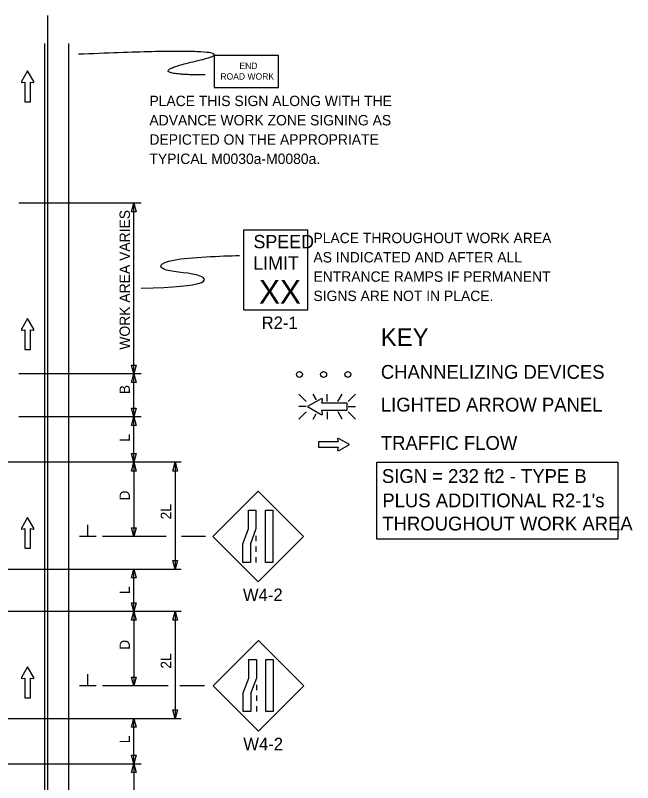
# Model space of a CAD drawing. Extents: x 16473 to 18475, y 7005 to 8296.
# Drawn here: x 17006 to 17422, y 7718 to 8234 of the extents above; entities that cross this region are included whole.
import ezdxf

# ---------------------------------------------------------------- set-up
doc = ezdxf.new("R2010")
doc.units = 0
for name, color, linetype in [('ALI_LEGAL_EX', 7, 'Continuous'), ('MT_SCRATCH_LEVEL_E', 7, 'Continuous'), ('PAVT_EDGE_EX', 7, 'Continuous'), ('TRAFFIC_SIGNS_PR', 7, 'Continuous'), ('TYPICAL_TEXT_DIMEN_EX', 7, 'Continuous'), ('TYPICAL_TEXT_DIMEN_PR', 7, 'Continuous')]:
    doc.layers.add(name, color=color, linetype=linetype)

msp = doc.modelspace()

# ---------------------------------------------------------------- linework, layer by layer
at = {"layer": 'ALI_LEGAL_EX'}
msp.add_line((17028.11, 8234.45), (17028.11, 7405.27), dxfattribs=at)
msp.add_line((17028.11, 8234.45), (17028.11, 7405.27), dxfattribs=at)
at = {"layer": 'MT_SCRATCH_LEVEL_E'}
for p, q in [((17014.65, 8197.08), (17010.54, 8189.84)), ((17018.8, 8189.84), (17014.65, 8197.08)), ((17011.03, 8189.16), (17012.8, 8189.47)), ((17012.8, 8189.47), (17012.8, 8176.22)), ((17016.54, 8176.22), (17016.54, 8189.47)), ((17016.54, 8189.47), (17018.32, 8189.16)), ((17012.8, 8176.22), (17016.54, 8176.22)), ((17014.65, 8030.22), (17010.54, 8022.98)), ((17018.8, 8022.98), (17014.65, 8030.22)), ((17011.03, 8022.29), (17012.8, 8022.61)), ((17012.8, 8022.61), (17012.8, 8009.35)), ((17016.54, 8009.35), (17016.54, 8022.61)), ((17016.54, 8022.61), (17018.32, 8022.29)), ((17012.8, 8009.35), (17016.54, 8009.35)), ((17231.32, 7945.36), (17224.08, 7949.47)), ((17223.71, 7947.21), (17210.45, 7947.21)), ((17210.45, 7947.21), (17210.45, 7943.47)), ((17223.4, 7948.99), (17223.71, 7947.21)), ((17224.08, 7941.21), (17231.32, 7945.36)), ((17210.45, 7943.47), (17223.71, 7943.47)), ((17223.71, 7943.47), (17223.4, 7941.69)), ((17014.65, 7896.31), (17010.54, 7889.07)), ((17018.8, 7889.07), (17014.65, 7896.31)), ((17011.03, 7888.39), (17012.8, 7888.7)), ((17012.8, 7888.7), (17012.8, 7875.45)), ((17016.54, 7875.45), (17016.54, 7888.7)), ((17016.54, 7888.7), (17018.32, 7888.39)), ((17012.8, 7875.45), (17016.54, 7875.45)), ((17014.65, 7795.67), (17010.54, 7788.43)), ((17018.8, 7788.43), (17014.65, 7795.67)), ((17011.03, 7787.74), (17012.8, 7788.06)), ((17012.8, 7788.06), (17012.8, 7774.8)), ((17016.54, 7774.8), (17016.54, 7788.06)), ((17016.54, 7788.06), (17018.32, 7787.74)), ((17012.8, 7774.8), (17016.54, 7774.8))]:
    msp.add_line(p, q, dxfattribs=at)
for centre, start, end in [((17010.95, 8189.62), 150.4248, 279.9638), ((17018.39, 8189.62), 260.0362, 29.7731), ((17010.95, 8022.75), 150.4248, 279.9638), ((17018.39, 8022.75), 260.0362, 29.7731), ((17223.85, 7949.06), 60.4248, 189.9638), ((17223.85, 7941.62), 170.0362, 299.7731), ((17010.95, 7888.85), 150.4248, 279.9638), ((17018.39, 7888.85), 260.0362, 29.7731), ((17010.95, 7788.2), 150.4248, 279.9638), ((17018.39, 7788.2), 260.0362, 29.7731)]:
    msp.add_arc(centre, 0.463, start, end, dxfattribs=at)
at = {"layer": 'PAVT_EDGE_EX'}
for p, q in [((17026.13, 8215.4), (17026.13, 7361.76)), ((17042.13, 8215.4), (17042.13, 7361.76))]:
    msp.add_line(p, q, dxfattribs=at)
at = {"layer": 'TRAFFIC_SIGNS_PR'}
for p, q in [((17160.26, 8090.06), (17203.46, 8090.06)), ((17160.26, 8036.06), (17160.26, 8090.06)), ((17203.46, 8036.06), (17203.46, 8090.06)), ((17160.26, 8036.06), (17203.46, 8036.06)), ((17197.35, 7979.37), (17202.28, 7974.43)), ((17209.11, 7975.54), (17206.91, 7979.37)), ((17216.43, 7974.43), (17216.43, 7979.37)), ((17223.67, 7974.43), (17226.52, 7979.37)), ((17230.58, 7974.43), (17235.52, 7979.37)), ((17202.28, 7970.88), (17197.35, 7970.88)), ((17230.58, 7970.88), (17235.52, 7970.88)), ((17197.35, 7962.39), (17202.28, 7967.32)), ((17206.86, 7962.39), (17208.98, 7966.05)), ((17216.43, 7967.32), (17216.43, 7962.39)), ((17226.56, 7962.39), (17223.71, 7967.32)), ((17230.58, 7967.32), (17235.52, 7962.38)), ((17169.85, 7913.91), (17139.3, 7883.36)), ((17200.39, 7883.36), (17169.85, 7913.91)), ((17139.3, 7883.36), (17169.85, 7852.82)), ((17168.44, 7883.91), (17168.44, 7880.31)), ((17169.85, 7852.82), (17200.39, 7883.36)), ((17168.44, 7876.71), (17168.44, 7873.11)), ((17168.44, 7869.51), (17168.44, 7865.91)), ((17170.1, 7813.41), (17139.55, 7782.86)), ((17200.65, 7782.86), (17170.1, 7813.41)), ((17139.55, 7782.86), (17170.1, 7752.32)), ((17168.7, 7783.42), (17168.7, 7779.82)), ((17170.1, 7752.32), (17200.65, 7782.86)), ((17168.7, 7776.22), (17168.7, 7772.62)), ((17168.7, 7769.02), (17168.7, 7765.42))]:
    msp.add_line(p, q, dxfattribs=at)
for points in [[(17140.4, 8185.82), (17183.6, 8185.82), (17183.6, 8207.42), (17140.4, 8207.42)], [(17168.44, 7901.07), (17168.44, 7888.49), (17164.68, 7878.49), (17164.68, 7865.91), (17159.63, 7865.91), (17159.63, 7878.49), (17163.39, 7888.49), (17163.39, 7901.07)], [(17179.85, 7901.07), (17179.85, 7865.91), (17174.79, 7865.91), (17174.79, 7901.07)], [(17168.7, 7800.57), (17168.7, 7787.99), (17164.94, 7778), (17164.94, 7765.42), (17159.88, 7765.42), (17159.88, 7778), (17163.64, 7787.99), (17163.64, 7800.57)], [(17180.1, 7800.57), (17180.1, 7765.42), (17175.05, 7765.42), (17175.05, 7800.57)]]:
    msp.add_lwpolyline(points, close=True, dxfattribs=at)
for points in [[(17212.36, 7976.15), (17203.07, 7970.88), (17212.36, 7965.56)], [(17213.24, 7966.18), (17212.84, 7968.45), (17229.85, 7968.45), (17229.85, 7973.25), (17212.84, 7973.25), (17213.24, 7975.53)]]:
    msp.add_lwpolyline(points, dxfattribs=at)
for centre in [(17197.69, 7992.56), (17213.99, 7992.56), (17230.29, 7992.56)]:
    msp.add_circle(centre, 2, dxfattribs=at)
for centre, radius, start, end in [((17212.65, 7975.63), 0.598, 350.7308, 118.8916), ((17212.65, 7966.08), 0.597, 241.4833, 9.9593)]:
    msp.add_arc(centre, radius, start, end, dxfattribs=at)
at = {"layer": 'TYPICAL_TEXT_DIMEN_EX'}
msp.add_lwpolyline([(17249.8, 7933.51), (17412.18, 7933.51), (17412.18, 7881.53), (17249.8, 7881.53)], close=True, dxfattribs=at)
at = {"layer": 'TYPICAL_TEXT_DIMEN_PR'}
for p, q in [((17091.13, 8107.91), (17008.73, 8107.91)), ((17084.56, 8102.05), (17086.13, 8107.91)), ((17086.13, 7993), (17086.13, 8107.91)), ((17086.13, 8107.91), (17087.7, 8102.05)), ((17086.13, 8102.05), (17084.56, 8102.05)), ((17087.7, 8102.05), (17086.13, 8102.05)), ((17086.13, 7993), (17084.56, 7998.86)), ((17084.56, 7998.86), (17086.13, 7998.86)), ((17086.13, 7998.86), (17087.7, 7998.86)), ((17087.7, 7998.86), (17086.13, 7993)), ((17091.13, 7993), (17008.73, 7993)), ((17084.56, 7987.14), (17086.13, 7993)), ((17086.13, 7963.95), (17086.13, 7993)), ((17086.13, 7993), (17087.7, 7987.14)), ((17086.13, 7987.14), (17084.56, 7987.14)), ((17087.7, 7987.14), (17086.13, 7987.14)), ((17086.13, 7963.95), (17084.56, 7969.81)), ((17084.56, 7969.81), (17086.13, 7969.81)), ((17086.13, 7969.81), (17087.7, 7969.81)), ((17087.7, 7969.81), (17086.13, 7963.95)), ((17091.13, 7963.95), (17008.73, 7963.95)), ((17084.56, 7958.08), (17086.13, 7963.95)), ((17086.13, 7933.38), (17086.13, 7963.95)), ((17086.13, 7963.95), (17087.7, 7958.08)), ((17086.13, 7958.08), (17084.56, 7958.08)), ((17087.7, 7958.08), (17086.13, 7958.08)), ((17086.13, 7933.38), (17084.56, 7939.24)), ((17084.56, 7939.24), (17086.13, 7939.24)), ((17086.13, 7939.24), (17087.7, 7939.24)), ((17087.7, 7939.24), (17086.13, 7933.38)), ((17118.17, 7933.38), (16987.03, 7933.38)), ((17084.56, 7927.52), (17086.13, 7933.38)), ((17086.13, 7933.38), (17086.13, 7883.38)), ((17086.13, 7933.38), (17087.7, 7927.52)), ((17112.36, 7927.52), (17113.93, 7933.38)), ((17113.93, 7933.38), (17115.5, 7927.52)), ((17113.93, 7933.38), (17113.93, 7861.38)), ((17086.13, 7927.52), (17084.56, 7927.52)), ((17087.7, 7927.52), (17086.13, 7927.52)), ((17113.93, 7927.52), (17112.36, 7927.52)), ((17115.5, 7927.52), (17113.93, 7927.52)), ((17055.25, 7883.38), (17055.25, 7891.17)), ((17086.13, 7883.38), (17084.56, 7889.24)), ((17084.56, 7889.24), (17086.13, 7889.24)), ((17086.13, 7889.24), (17087.7, 7889.24)), ((17087.7, 7889.24), (17086.13, 7883.38)), ((17113.93, 7888.25), (17113.93, 7884.48)), ((17060.88, 7883.38), (17049.63, 7883.38)), ((17108.04, 7883.38), (17065.13, 7883.38)), ((17134.41, 7883.38), (17118.32, 7883.38)), ((17113.93, 7861.38), (17112.36, 7867.24)), ((17112.36, 7867.24), (17113.93, 7867.24)), ((17113.93, 7867.24), (17115.5, 7867.24)), ((17115.5, 7867.24), (17113.93, 7861.38)), ((16987.03, 7861.38), (17118.17, 7861.38)), ((17084.56, 7855.52), (17086.13, 7861.38)), ((17086.13, 7832.82), (17086.13, 7861.38)), ((17086.13, 7861.38), (17087.7, 7855.52)), ((17086.13, 7855.52), (17084.56, 7855.52)), ((17087.7, 7855.52), (17086.13, 7855.52)), ((17086.13, 7832.82), (17084.56, 7838.68)), ((17084.56, 7838.68), (17086.13, 7838.68)), ((17086.13, 7838.68), (17087.7, 7838.68)), ((17087.7, 7838.68), (17086.13, 7832.82)), ((17118.17, 7832.82), (16955.35, 7832.82)), ((17084.56, 7826.96), (17086.13, 7832.82)), ((17086.13, 7832.82), (17086.13, 7782.82)), ((17086.13, 7832.82), (17087.7, 7826.96)), ((17112.36, 7826.96), (17113.93, 7832.82)), ((17113.93, 7832.82), (17115.5, 7826.96)), ((17113.93, 7832.82), (17113.93, 7760.82)), ((17086.13, 7826.96), (17084.56, 7826.96)), ((17087.7, 7826.96), (17086.13, 7826.96)), ((17113.93, 7826.96), (17112.36, 7826.96)), ((17115.5, 7826.96), (17113.93, 7826.96)), ((17055.25, 7782.82), (17055.25, 7790.61)), ((17086.13, 7782.82), (17084.56, 7788.68)), ((17084.56, 7788.68), (17086.13, 7788.68)), ((17086.13, 7788.68), (17087.7, 7788.68)), ((17087.7, 7788.68), (17086.13, 7782.82)), ((17113.93, 7787.69), (17113.93, 7783.92)), ((17060.88, 7782.82), (17049.63, 7782.82)), ((17109.23, 7782.82), (17065.13, 7782.82)), ((17133.84, 7782.82), (17117.1, 7782.82)), ((17113.93, 7760.82), (17112.36, 7766.68)), ((17112.36, 7766.68), (17113.93, 7766.68)), ((17113.93, 7766.68), (17115.5, 7766.68)), ((17115.5, 7766.68), (17113.93, 7760.82)), ((16954.73, 7760.82), (17118.17, 7760.82)), ((17084.56, 7754.96), (17086.13, 7760.82)), ((17086.13, 7730.26), (17086.13, 7760.82)), ((17086.13, 7760.82), (17087.7, 7754.96)), ((17086.13, 7754.96), (17084.56, 7754.96)), ((17087.7, 7754.96), (17086.13, 7754.96)), ((17086.13, 7730.26), (17084.56, 7736.12)), ((17084.56, 7736.12), (17086.13, 7736.12)), ((17086.13, 7736.12), (17087.7, 7736.12)), ((17087.7, 7736.12), (17086.13, 7730.26)), ((16931.74, 7730.26), (17091.13, 7730.26)), ((17084.56, 7724.39), (17086.13, 7730.26)), ((17086.13, 7730.26), (17086.13, 7680.26)), ((17086.13, 7730.26), (17087.7, 7724.39)), ((17086.13, 7724.39), (17084.56, 7724.39)), ((17087.7, 7724.39), (17086.13, 7724.39))]:
    msp.add_line(p, q, dxfattribs=at)
for points, degree in [([(17134.14, 8194.33), (17086.91, 8194.33), (17171.93, 8213.68), (17048.83, 8208.19)], 2), ([(17091.19, 8050.62), (17137.39, 8051.56), (17136.23, 8061.21), (17102.53, 8061.21), (17102.53, 8070.87), (17145.39, 8072.39), (17157.3, 8072.65)], 3), ([(17211.6, 8047.79), (17211.61, 8047.79), (17211.62, 8047.79), (17211.62, 8047.79)], 2)]:
    msp.add_open_spline(points, degree=degree, dxfattribs=at)

# ---------------------------------------------------------------- texts
at = {"layer": 'TRAFFIC_SIGNS_PR'}
for s, height, p in [('END', 4.31, (17157.28, 8198.34)), ('ROAD WORK', 4.31, (17144.46, 8191.15)), ('PLACE THIS SIGN ALONG WITH THE', 7, (17096.69, 8173.32)), ('ADVANCE WORK ZONE SIGNING AS', 7, (17096.69, 8160.32)), ('DEPICTED ON THE APPROPRIATE', 7, (17096.69, 8147.32)), ('TYPICAL M0030a-M0080a.', 7, (17096.69, 8134.32)), ('SPEED', 9, (17166.74, 8077.53)), ('PLACE THROUGHOUT WORK AREA', 7, (17207.14, 8081)), ('AS INDICATED AND AFTER ALL', 7, (17207.14, 8068)), ('LIMIT', 9, (17166.56, 8063.13)), ('ENTRANCE RAMPS IF PERMANENT', 7, (17207.14, 8055)), ('XX', 15.785, (17170.51, 8040.29)), ('SIGNS ARE NOT IN PLACE.', 7, (17207.14, 8042)), ('R2-1', 8.37, (17172.27, 8023.19)), ('W4-2', 8.37, (17159.67, 7839.95)), ('W4-2', 8.37, (17159.93, 7739.45))]:
    msp.add_text(s, height=height, dxfattribs=at).set_placement(p)
at = {"layer": 'TYPICAL_TEXT_DIMEN_EX'}
for s, height, p in [('KEY', 12, (17252.53, 8011.67)), ('CHANNELIZING DEVICES', 9.3, (17252.53, 7989.62)), ('LIGHTED ARROW PANEL', 9.3, (17252.53, 7967.57)), ('TRAFFIC FLOW', 9.3, (17252.53, 7941.77)), ('SIGN = 232 ft2 - TYPE B', 9.3, (17253.24, 7919.46)), ("PLUS ADDITIONAL R2-1's", 9.3, (17253.52, 7903.05)), ('THROUGHOUT WORK AREA', 9.3, (17253.52, 7887.45))]:
    msp.add_text(s, height=height, dxfattribs=at).set_placement(p)
at = {"layer": 'TYPICAL_TEXT_DIMEN_PR'}
for s, p in [('WORK AREA VARIES', (17083.57, 8009.22)), ('B', (17083.57, 7979.21)), ('L', (17083.57, 7947.24)), ('D', (17083.57, 7907.6)), ('2L', (17111.37, 7894.88)), ('L', (17083.57, 7844.67)), ('D', (17083.57, 7807.04)), ('2L', (17111.37, 7794.32)), ('L', (17083.57, 7744.11))]:
    msp.add_text(s, height=7, rotation=90, dxfattribs=at).set_placement(p)

doc.saveas('drawing.dxf')
